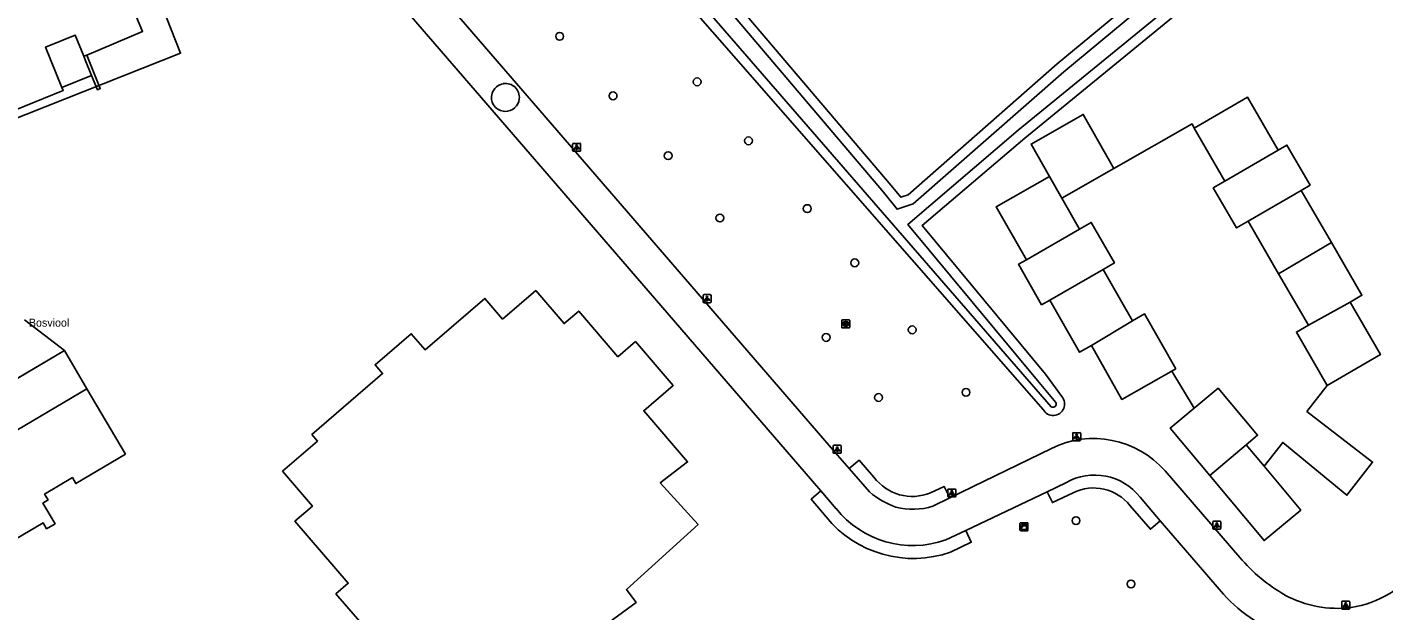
# Model space of a CAD drawing. Extents: x 156664 to 157568, y 383571 to 384421.
# Drawn here: x 156803.6 to 156973.2, y 383759.7 to 383832.6 of the extents above; entities that cross this region are included whole.
import ezdxf

# ---------------------------------------------------------------- set-up
doc = ezdxf.new("R2010")
doc.units = 0
for name, color, linetype in [('IMGEO_Berm_open', 7, 'Continuous'), ('IMGEO_Boom', 7, 'Continuous'), ('IMGEO_Groenvoorziening', 7, 'Continuous'), ('IMGEO_Kast', 7, 'Continuous'), ('IMGEO_Lichtpunt', 7, 'Continuous'), ('IMGEO_Muur', 7, 'Continuous'), ('IMGEO_Openbare_ruimte_label', 7, 'Continuous'), ('IMGEO_Pand', 7, 'Continuous'), ('IMGEO_Pand_overbouw', 7, 'Continuous'), ('IMGEO_Pand_vergunning_verleend', 7, 'Continuous'), ('IMGEO_Rijbaan_lokaal_gesloten', 7, 'Continuous'), ('IMGEO_Rijbaan_lokaal_open', 7, 'Continuous'), ('IMGEO_Rioolput', 7, 'Continuous'), ('IMGEO_Voetpad_op_trap', 7, 'Continuous'), ('IMGEO_Waterloop', 7, 'Continuous')]:
    doc.layers.add(name, color=color, linetype=linetype)

msp = doc.modelspace()

# ---------------------------------------------------------------- linework, layer by layer
at = {"layer": 'IMGEO_Berm_open'}
for points in [[(156906.37, 383777.46), (156907.59, 383778.51), (156909.46, 383776.35)], [(156903.48, 383771.4), (156901.63, 383773.6), (156902.83, 383774.64)], [(156916.53, 383774.41), (156918.22, 383775.22), (156918.95, 383773.77)], [(156934.36, 383774.42), (156931.77, 383773.19), (156931.1, 383774.53)], [(156945.24, 383770.91), (156944.02, 383769.87), (156941.49, 383772.79)], [(156920.96, 383769.71), (156921.62, 383768.24), (156919.03, 383767.01)]]:
    msp.add_lwpolyline(points, dxfattribs=at)
for centre, radius, start, end in [((156914.26, 383779.97), 6.01, 217.0535, 292.2663), ((156936.92, 383769.23), 5.79, 38.0194, 116.3179), ((156914.36, 383780.2), 13.99, 218.969, 289.5075)]:
    msp.add_arc(centre, radius, start, end, dxfattribs=at)
at = {"layer": 'IMGEO_Boom'}
for centre in [(156870.17, 383831.43), (156887.36, 383825.74), (156876.85, 383823.99), (156893.78, 383818.38), (156883.74, 383816.52), (156901.12, 383809.91), (156890.2, 383808.74), (156907.06, 383803.13), (156903.48, 383793.82), (156914.24, 383794.77), (156920.97, 383786.96), (156910.03, 383786.31), (156934.71, 383770.94), (156941.59, 383763.03)]:
    msp.add_circle(centre, 0.489, dxfattribs=at)
at = {"layer": 'IMGEO_Groenvoorziening'}
for points in [[(156851.52, 383893.46), (156854.87, 383880.1), (156855.95, 383876.48), (156875.13, 383855.23), (156891.46, 383836.51), (156911.62, 383812.79), (156912.8, 383811.32), (156913.72, 383811.62), (156932.37, 383827.97), (156950.38, 383842.94), (156962.3, 383852.37), (156962.64, 383852.87), (156967.11, 383858.58), (156983.42, 383879.38)], [(156930.61, 383784.8), (156881.09, 383841.39), (156853.84, 383872.65), (156852.3, 383874.71), (156848.11, 383890.33), (156847.87, 383891.87)], [(156968.21, 383852.09), (156968.15, 383852.02), (156968.1, 383851.94), (156968.04, 383851.87), (156967.54, 383851.36), (156947.1, 383834.06), (156928.3, 383818.71), (156915.48, 383807.78), (156930.92, 383789.21), (156932.93, 383786.44)]]:
    msp.add_lwpolyline(points, dxfattribs=at)
msp.add_arc((156931.86, 383785.5), 1.43, 208.972, 41.1243, dxfattribs=at)
at = {"layer": 'IMGEO_Kast'}
for p, q in [((156927.71, 383769.76), (156927.71, 383770.6)), ((156927.71, 383770.6), (156927.71, 383769.76)), ((156927.79, 383770.68), (156928.63, 383770.68)), ((156928.63, 383770.68), (156927.79, 383770.68)), ((156928.71, 383770.61), (156928.71, 383769.77)), ((156928.71, 383769.77), (156928.71, 383770.61)), ((156928.64, 383769.68), (156927.8, 383769.68)), ((156927.8, 383769.68), (156928.64, 383769.68))]:
    msp.add_line(p, q, dxfattribs=at)
for points in [[(156927.91, 383770.47), (156928.51, 383770.47), (156928.51, 383770.39), (156927.91, 383770.39), (156927.91, 383770.47)], [(156927.91, 383770.3), (156928.51, 383770.3), (156928.51, 383769.81), (156927.91, 383769.81), (156927.91, 383770.3)]]:
    msp.add_lwpolyline(points, dxfattribs=at)
msp.add_circle((156927.99, 383770.15), 0.0377, dxfattribs=at)
for centre, start, end in [((156927.79, 383770.6), 92.4484, 184.2845), ((156927.79, 383770.6), 92.4484, 184.2845), ((156928.63, 383770.6), 2.4484, 94.2845), ((156928.63, 383770.6), 2.4484, 94.2845), ((156927.79, 383769.76), 182.4484, 274.2845), ((156927.79, 383769.76), 182.4484, 274.2845), ((156928.63, 383769.76), 272.4484, 4.2845), ((156928.63, 383769.76), 272.4484, 4.2845)]:
    msp.add_arc(centre, 0.0779, start, end, dxfattribs=at)
at = {"layer": 'IMGEO_Lichtpunt'}
for p, q in [((156871.8, 383817.97), (156871.8, 383817.16)), ((156871.8, 383817.97), (156871.8, 383817.16)), ((156872.7, 383818.06), (156871.9, 383818.06)), ((156872.7, 383818.06), (156871.9, 383818.06)), ((156872.8, 383817.16), (156872.8, 383817.97)), ((156872.8, 383817.16), (156872.8, 383817.97)), ((156871.9, 383817.07), (156872.7, 383817.07)), ((156871.9, 383817.07), (156872.7, 383817.07)), ((156888.1, 383799.06), (156888.1, 383798.26)), ((156888.1, 383799.06), (156888.1, 383798.26)), ((156889, 383799.16), (156888.2, 383799.16)), ((156889, 383799.16), (156888.2, 383799.16)), ((156888.2, 383798.16), (156889, 383798.16)), ((156888.2, 383798.16), (156889, 383798.16)), ((156889.1, 383798.26), (156889.1, 383799.06)), ((156889.1, 383798.26), (156889.1, 383799.06)), ((156934.3, 383781.83), (156934.3, 383781.02)), ((156934.3, 383781.83), (156934.3, 383781.02)), ((156935.2, 383781.92), (156934.39, 383781.92)), ((156935.2, 383781.92), (156934.39, 383781.92)), ((156934.39, 383780.92), (156935.2, 383780.92)), ((156934.39, 383780.92), (156935.2, 383780.92)), ((156935.3, 383781.02), (156935.3, 383781.83)), ((156935.3, 383781.02), (156935.3, 383781.83)), ((156904.37, 383780.26), (156904.37, 383779.45)), ((156904.37, 383780.26), (156904.37, 383779.45)), ((156905.27, 383780.35), (156904.46, 383780.35)), ((156905.27, 383780.35), (156904.46, 383780.35)), ((156904.46, 383779.36), (156905.27, 383779.36)), ((156904.46, 383779.36), (156905.27, 383779.36)), ((156905.36, 383779.45), (156905.36, 383780.26)), ((156905.36, 383779.45), (156905.36, 383780.26)), ((156918.69, 383774.79), (156918.69, 383773.98)), ((156918.69, 383774.79), (156918.69, 383773.98)), ((156919.59, 383774.88), (156918.79, 383774.88)), ((156919.59, 383774.88), (156918.79, 383774.88)), ((156918.79, 383773.89), (156919.59, 383773.89)), ((156918.79, 383773.89), (156919.59, 383773.89)), ((156919.69, 383773.98), (156919.69, 383774.79)), ((156919.69, 383773.98), (156919.69, 383774.79)), ((156951.82, 383770.77), (156951.82, 383769.96)), ((156951.82, 383770.77), (156951.82, 383769.96)), ((156952.72, 383770.87), (156951.92, 383770.87)), ((156952.72, 383770.87), (156951.92, 383770.87)), ((156952.82, 383769.96), (156952.82, 383770.77)), ((156952.82, 383769.96), (156952.82, 383770.77)), ((156951.92, 383769.87), (156952.72, 383769.87)), ((156951.92, 383769.87), (156952.72, 383769.87)), ((156967.93, 383760.79), (156967.93, 383759.98)), ((156967.93, 383760.79), (156967.93, 383759.98)), ((156968.83, 383760.88), (156968.02, 383760.88)), ((156968.83, 383760.88), (156968.02, 383760.88)), ((156968.92, 383759.98), (156968.92, 383760.79)), ((156968.92, 383759.98), (156968.92, 383760.79)), ((156968.02, 383759.89), (156968.83, 383759.89)), ((156968.02, 383759.89), (156968.83, 383759.89))]:
    msp.add_line(p, q, dxfattribs=at)
for points in [[(156872.18, 383817.63), (156872.21, 383817.61), (156872.03, 383817.34), (156871.99, 383817.37), (156872.18, 383817.63)], [(156872.28, 383817.59), (156872.33, 383817.59), (156872.33, 383817.26), (156872.28, 383817.26), (156872.28, 383817.59)], [(156872.39, 383817.61), (156872.43, 383817.63), (156872.61, 383817.37), (156872.57, 383817.34), (156872.39, 383817.61)], [(156888.48, 383798.73), (156888.51, 383798.7), (156888.33, 383798.44), (156888.29, 383798.46), (156888.48, 383798.73)], [(156888.58, 383798.68), (156888.62, 383798.68), (156888.62, 383798.36), (156888.58, 383798.36), (156888.58, 383798.68)], [(156888.69, 383798.7), (156888.73, 383798.73), (156888.91, 383798.46), (156888.87, 383798.44), (156888.69, 383798.7)], [(156934.67, 383781.49), (156934.71, 383781.46), (156934.52, 383781.2), (156934.49, 383781.23), (156934.67, 383781.49)], [(156934.77, 383781.44), (156934.82, 383781.44), (156934.82, 383781.12), (156934.77, 383781.12), (156934.77, 383781.44)], [(156934.88, 383781.46), (156934.92, 383781.49), (156935.11, 383781.23), (156935.07, 383781.2), (156934.88, 383781.46)], [(156904.74, 383779.92), (156904.78, 383779.89), (156904.59, 383779.63), (156904.55, 383779.66), (156904.74, 383779.92)], [(156904.84, 383779.87), (156904.89, 383779.87), (156904.89, 383779.55), (156904.84, 383779.55), (156904.84, 383779.87)], [(156904.95, 383779.89), (156904.99, 383779.92), (156905.18, 383779.66), (156905.14, 383779.63), (156904.95, 383779.89)], [(156919.07, 383774.45), (156919.1, 383774.42), (156918.92, 383774.16), (156918.88, 383774.19), (156919.07, 383774.45)], [(156919.17, 383774.4), (156919.22, 383774.4), (156919.22, 383774.08), (156919.17, 383774.08), (156919.17, 383774.4)], [(156919.28, 383774.42), (156919.32, 383774.45), (156919.5, 383774.19), (156919.46, 383774.16), (156919.28, 383774.42)], [(156952.2, 383770.43), (156952.24, 383770.41), (156952.05, 383770.14), (156952.01, 383770.17), (156952.2, 383770.43)], [(156952.41, 383770.41), (156952.45, 383770.43), (156952.63, 383770.17), (156952.6, 383770.14), (156952.41, 383770.41)], [(156952.3, 383770.39), (156952.35, 383770.39), (156952.35, 383770.06), (156952.3, 383770.06), (156952.3, 383770.39)], [(156968.3, 383760.45), (156968.34, 383760.42), (156968.15, 383760.16), (156968.11, 383760.19), (156968.3, 383760.45)], [(156968.4, 383760.4), (156968.45, 383760.4), (156968.45, 383760.08), (156968.4, 383760.08), (156968.4, 383760.4)], [(156968.51, 383760.42), (156968.55, 383760.45), (156968.74, 383760.19), (156968.7, 383760.16), (156968.51, 383760.42)]]:
    msp.add_lwpolyline(points, dxfattribs=at)
for centre in [(156872.3, 383817.77), (156888.6, 383798.86), (156934.8, 383781.62), (156904.87, 383780.06), (156919.19, 383774.59), (156952.32, 383770.57), (156968.43, 383760.59)]:
    msp.add_circle(centre, 0.0994, dxfattribs=at)
for centre, start, end in [((156871.9, 383817.97), 90, 180), ((156871.9, 383817.97), 90, 180), ((156872.7, 383817.97), 0, 90), ((156872.7, 383817.97), 0, 90), ((156871.9, 383817.16), 180, 270), ((156871.9, 383817.16), 180, 270), ((156872.7, 383817.16), 270, 0), ((156872.7, 383817.16), 270, 360), ((156888.2, 383799.06), 90, 180), ((156888.2, 383799.06), 90, 180), ((156888.2, 383798.26), 180, 270), ((156888.2, 383798.26), 180, 270), ((156889, 383799.06), 0, 90), ((156889, 383799.06), 0, 90), ((156889, 383798.26), 270, 0), ((156889, 383798.26), 270, 360), ((156934.39, 383781.83), 90, 180), ((156934.39, 383781.83), 90, 180), ((156934.39, 383781.02), 180, 270), ((156934.39, 383781.02), 180, 270), ((156935.2, 383781.83), 0, 90), ((156935.2, 383781.83), 0, 90), ((156935.2, 383781.02), 270, 0), ((156935.2, 383781.02), 270, 360), ((156904.46, 383780.26), 90, 180), ((156904.46, 383780.26), 90, 180), ((156904.46, 383779.45), 180, 270), ((156904.46, 383779.45), 180, 270), ((156905.27, 383780.26), 0, 90), ((156905.27, 383780.26), 0, 90), ((156905.27, 383779.45), 270, 0), ((156905.27, 383779.45), 270, 360), ((156918.79, 383774.79), 90, 180), ((156918.79, 383774.79), 90, 180), ((156918.79, 383773.98), 180, 270), ((156918.79, 383773.98), 180, 270), ((156919.59, 383774.79), 0, 90), ((156919.59, 383774.79), 0, 90), ((156919.59, 383773.98), 270, 0), ((156919.59, 383773.98), 270, 360), ((156951.92, 383770.77), 90, 180), ((156951.92, 383770.77), 90, 180), ((156952.72, 383770.77), 0, 90), ((156952.72, 383770.77), 0, 90), ((156951.92, 383769.96), 180, 270), ((156951.92, 383769.96), 180, 270), ((156952.72, 383769.96), 270, 0), ((156952.72, 383769.96), 270, 360), ((156968.02, 383760.79), 90, 180), ((156968.02, 383760.79), 90, 180), ((156968.83, 383760.79), 0, 90), ((156968.83, 383760.79), 0, 90), ((156968.02, 383759.98), 180, 270), ((156968.02, 383759.98), 180, 270), ((156968.83, 383759.98), 270, 0), ((156968.83, 383759.98), 270, 360)]:
    msp.add_arc(centre, 0.0946, start, end, dxfattribs=at)
at = {"layer": 'IMGEO_Muur'}
for points in [[(156810.69, 383828.93), (156810.88, 383828.48), (156811.66, 383826.54)], [(156811.66, 383826.54), (156812.39, 383824.75), (156812.75, 383824.9), (156811.06, 383829.07)]]:
    msp.add_lwpolyline(points, dxfattribs=at)
at = {"layer": 'IMGEO_Pand'}
for points in [[(156807.97, 383825.04), (156808.12, 383824.67), (156800.74, 383821.68), (156799.6, 383824.5), (156795.42, 383822.79), (156793.14, 383828.33), (156790.36, 383827.19), (156787.63, 383833.86), (156788.46, 383834.21), (156786.93, 383837.92), (156786.1, 383837.58), (156783.38, 383844.24), (156784.76, 383844.81), (156780.2, 383855.94), (156794.06, 383861.61), (156795.92, 383862.38), (156798.21, 383863.31), (156804.04, 383865.7)], [(156810.75, 383865.21), (156812.32, 383865.86), (156814.59, 383860.3), (156817.38, 383861.45), (156822.06, 383849.94), (156821.46, 383849.69), (156823.74, 383844.14), (156820.2, 383842.68), (156822.5, 383837.14), (156816.87, 383834.83), (156818.05, 383832.04), (156811.06, 383829.07)], [(156810.69, 383828.93), (156809.62, 383831.57), (156805.93, 383830.08), (156807.97, 383825.04)], [(156811.06, 383829.07), (156810.69, 383828.93)], [(156800.36, 383781.07), (156811.07, 383787.41), (156815.9, 383779.24)], [(156815.9, 383779.24), (156809.71, 383775.57), (156809.27, 383776.31), (156805.8, 383774.26), (156806.24, 383773.52), (156805.58, 383773.12), (156807.1, 383770.55), (156806.05, 383769.93), (156805.61, 383770.67), (156802.14, 383768.64)]]:
    msp.add_lwpolyline(points, dxfattribs=at)
at = {"layer": 'IMGEO_Pand_overbouw'}
msp.add_lwpolyline([(156808.27, 383792.17), (156797.55, 383785.84), (156799.07, 383783.25), (156783.98, 383774.32), (156782.46, 383776.91), (156766.58, 383767.51), (156769.38, 383762.77), (156785.21, 383772.14), (156786.73, 383769.55), (156801.89, 383778.49), (156800.36, 383781.07), (156811.07, 383787.41)], close=True, dxfattribs=at)
at = {"layer": 'IMGEO_Pand_vergunning_verleend'}
for points in [[(156780.47, 383854.21), (156810.42, 383866.07), (156813.71, 383857.94), (156816.75, 383859.15), (156823.56, 383841.94), (156820.43, 383840.7), (156822.3, 383835.97), (156820.45, 383835.23), (156822.8, 383829.31), (156801.04, 383820.7), (156799.83, 383823.75), (156795.74, 383822.13), (156793.48, 383827.86), (156790.01, 383826.48), (156783.66, 383842.52), (156784.9, 383843.01), (156780.47, 383854.21)], [(156949.49, 383819.94), (156956.15, 383823.81), (156959.98, 383817.2)], [(156931.39, 383813.92), (156929.09, 383817.97), (156935.61, 383821.68), (156939.45, 383814.93)], [(156939.45, 383814.93), (156949.22, 383820.49), (156949.49, 383819.94)], [(156949.49, 383819.94), (156953.32, 383813.34)], [(156953.32, 383813.34), (156959.98, 383817.2)], [(156959.98, 383817.2), (156961.07, 383817.84), (156963.97, 383812.84), (156962.85, 383812.19)], [(156932.94, 383811.23), (156939.45, 383814.93)], [(156939.45, 383814.93), (156939.45, 383814.93), (156932.94, 383811.23)], [(156928.52, 383803.51), (156924.75, 383810.15), (156931.39, 383813.92)], [(156932.94, 383811.23), (156931.39, 383813.92)], [(156953.32, 383813.34), (156951.87, 383812.5), (156954.78, 383807.49), (156956.23, 383808.33)], [(156935.14, 383807.36), (156932.94, 383811.23)], [(156956.23, 383808.33), (156962.85, 383812.19)], [(156962.85, 383812.19), (156966.64, 383805.66)], [(156938.11, 383802.32), (156939.51, 383803.12), (156936.62, 383808.19), (156935.14, 383807.36)], [(156956.23, 383808.33), (156960.03, 383801.78)], [(156935.14, 383807.36), (156928.52, 383803.51)], [(156960.03, 383801.78), (156966.64, 383805.66)], [(156966.64, 383805.66), (156970.45, 383799.09), (156968.97, 383798.23)], [(156931.45, 383798.49), (156930.41, 383797.89), (156927.54, 383802.95), (156928.52, 383803.51)], [(156938.11, 383802.32), (156931.45, 383798.49)], [(156941.77, 383795.9), (156938.11, 383802.32)], [(156960.03, 383801.78), (156963.76, 383795.35)], [(156835.53, 383777.13), (156839.89, 383780.88), (156839.2, 383781.69), (156848.05, 383789.31), (156847.11, 383790.4), (156851.63, 383794.28), (156853.36, 383792.27), (156860.83, 383798.69), (156863.05, 383796.11), (156867.18, 383799.67), (156870.73, 383795.54), (156872.56, 383797.11), (156877.46, 383791.41), (156879.64, 383793.29), (156884.35, 383787.8), (156880.69, 383784.66), (156886.17, 383778.28), (156882.75, 383775.65), (156887.48, 383770.46), (156878.55, 383762.33), (156879.73, 383760.73), (156871.37, 383754.59)], [(156936.63, 383792.81), (156935.16, 383791.97), (156931.45, 383798.49)], [(156963.76, 383795.35), (156968.97, 383798.23)], [(156968.97, 383798.23), (156972.77, 383791.68), (156966.12, 383787.83)], [(156941.77, 383795.9), (156936.63, 383792.81)], [(156947.18, 383789.89), (156943.28, 383796.76), (156941.77, 383795.9)], [(156963.76, 383795.35), (156962.26, 383794.48), (156966.12, 383787.83)], [(156947.18, 383789.89), (156940.46, 383786.07), (156936.63, 383792.81)], [(156949.49, 383785), (156946.71, 383789.62), (156947.18, 383789.89)], [(156955.98, 383780.41), (156957.41, 383781.6), (156952.48, 383787.5), (156949.49, 383785)], [(156966.12, 383787.83), (156963.58, 383784.58), (156971.78, 383778.26), (156968.58, 383774.11), (156960.55, 383780.7), (156958.23, 383777.73)], [(156951.44, 383776.57), (156946.49, 383782.49), (156949.49, 383785)], [(156955.98, 383780.41), (156951.44, 383776.57)], [(156958.23, 383777.73), (156958.22, 383777.72), (156955.98, 383780.41)], [(156955.98, 383780.41), (156958.23, 383777.73)], [(156958.23, 383777.73), (156962.8, 383772.25), (156958.23, 383768.44), (156951.44, 383776.57)], [(156846.52, 383756.78), (156842.21, 383761.79), (156843.75, 383763.11), (156837.08, 383770.87), (156839.28, 383772.76), (156835.53, 383777.13)]]:
    msp.add_lwpolyline(points, dxfattribs=at)
at = {"layer": 'IMGEO_Rijbaan_lokaal_gesloten'}
for centre, radius, start, end in [((156863.39, 383823.78), 1.74, 130.0856, 169.5908), ((156863.4, 383823.8), 1.73, 98.7141, 130.6426), ((156863.4, 383823.8), 1.74, 353.8037, 98.8143), ((156863.39, 383823.79), 1.74, 169.6525, 268.2313), ((156863.39, 383823.8), 1.75, 311.4273, 353.6497), ((156863.39, 383823.79), 1.74, 268.2893, 311.8666)]:
    msp.add_arc(centre, radius, start, end, dxfattribs=at)
at = {"layer": 'IMGEO_Rijbaan_lokaal_open'}
for points in [[(156820.25, 383877.09), (156862.92, 383827.69), (156866.64, 383823.38), (156904.91, 383779.13), (156906.37, 383777.46)], [(156822.23, 383867.92), (156859.63, 383824.66), (156863.33, 383820.38), (156901.78, 383775.88), (156902.83, 383774.64)], [(156803.29, 383796.01), (156808.28, 383792.18), (156766.72, 383767.6)], [(156918.95, 383773.77), (156931.63, 383779.95)], [(156908.89, 383774.52), (156906.37, 383777.46)], [(156931.1, 383774.53), (156933.46, 383775.67)], [(156945.85, 383777.14), (156955.18, 383766.34)], [(156902.83, 383774.64), (156904.73, 383772.43)], [(156920.96, 383769.71), (156931.1, 383774.53)], [(156942.73, 383773.87), (156945.24, 383770.91)], [(156918.95, 383773.77), (156916.83, 383772.74)], [(156945.24, 383770.91), (156953.13, 383761.76)], [(156918.43, 383768.53), (156920.96, 383769.71)]]:
    msp.add_lwpolyline(points, dxfattribs=at)
for centre, radius, start, end in [((156936.92, 383769.3), 11.89, 41.2931, 116.3849), ((156937.05, 383769.42), 7.21, 38.1257, 119.8685), ((156916.12, 383783.25), 11.33, 230.4057, 249.8257), ((156914.32, 383780.11), 12.29, 218.648, 289.5186), ((156914.29, 383781.08), 8.72, 256.156, 286.9403), ((156971.37, 383780.07), 21.22, 220.3019, 240.2427), ((156966.98, 383773.49), 13.57, 279.0659, 321.884), ((156967.28, 383774.49), 19.03, 221.9777, 237.3164), ((156967.43, 383773.9), 13.92, 241.6944, 276.9468)]:
    msp.add_arc(centre, radius, start, end, dxfattribs=at)
at = {"layer": 'IMGEO_Rioolput'}
for p, q in [((156905.43, 383795.08), (156905.43, 383795.93)), ((156905.51, 383796.01), (156906.36, 383796.01)), ((156906.44, 383795.93), (156906.44, 383795.08)), ((156906.36, 383795.01), (156905.51, 383795.01)), ((156905.92, 383795.79), (156905.95, 383795.79)), ((156905.94, 383795.23), (156905.92, 383795.23))]:
    msp.add_line(p, q, dxfattribs=at)
for points in [[(156905.43, 383795.08), (156905.43, 383795.93)], [(156905.51, 383796.01), (156906.36, 383796.01)], [(156906.44, 383795.93), (156906.44, 383795.08)], [(156906.36, 383795.01), (156905.51, 383795.01)], [(156906.02, 383795.71), (156905.77, 383795.71), (156905.77, 383795.31)], [(156905.77, 383795.31), (156905.9, 383795.31), (156905.9, 383795.47), (156905.91, 383795.47)], [(156905.95, 383795.63), (156905.9, 383795.63), (156905.9, 383795.55)], [(156905.9, 383795.55), (156905.95, 383795.55)], [(156905.95, 383795.44), (156906.02, 383795.31), (156906.16, 383795.31), (156906.1, 383795.43)]]:
    msp.add_lwpolyline(points, dxfattribs=at)
for centre, radius, start, end in [((156905.51, 383795.93), 0.0765, 91.552, 178.448), ((156905.51, 383795.93), 0.0765, 91.552, 178.448), ((156906.36, 383795.93), 0.0765, 1.552, 88.448), ((156906.36, 383795.93), 0.0765, 1.552, 88.448), ((156905.51, 383795.08), 0.0765, 181.552, 268.448), ((156905.51, 383795.08), 0.0765, 181.552, 268.448), ((156905.9, 383795.42), 0.0533, 26.0293, 88.6989), ((156905.95, 383795.53), 0.0964, 77.0061, 93.1865), ((156905.93, 383795.74), 0.19, 274.7715, 282.9687), ((156905.97, 383795.59), 0.0378, 276.6634, 79.6772), ((156906.02, 383795.6), 0.109, 350.3612, 89.416), ((156906.02, 383795.6), 0.112, 277.5842, 350.9817), ((156906, 383795.38), 0.108, 29.5134, 73.7905), ((156906.36, 383795.08), 0.0765, 271.552, 358.448), ((156906.36, 383795.08), 0.0765, 271.552, 358.448)]:
    msp.add_arc(centre, radius, start, end, dxfattribs=at)
for centre, major_axis, ratio, start_param, end_param in [((156905.92, 383795.51), (-0.387, 0.002), 0.722429, 4.712389, 7.853982), ((156905.95, 383795.51), (-0.39, 0.002), 0.717154, 1.570796, 4.712389)]:
    msp.add_ellipse(centre, major_axis=major_axis, ratio=ratio, start_param=start_param, end_param=end_param, dxfattribs=at)
at = {"layer": 'IMGEO_Voetpad_op_trap'}
msp.add_lwpolyline([(156807.97, 383825.04), (156811.66, 383826.54)], dxfattribs=at)
at = {"layer": 'IMGEO_Waterloop'}
for points in [[(156931.62, 383785.15), (156882.05, 383842.23), (156854.83, 383873.45), (156853.47, 383875.28), (156849.46, 383890.63), (156849.07, 383892.88)], [(156850.28, 383893.2), (156853.64, 383879.76), (156854.82, 383875.84), (156874.18, 383854.39), (156890.49, 383835.68), (156910.64, 383811.98), (156912.36, 383809.83), (156914.36, 383810.5), (156933.19, 383827), (156951.18, 383841.95), (156963.24, 383851.49), (156963.69, 383852.15)], [(156986.12, 383878.75), (156986.22, 383878.47), (156986.2, 383878.22), (156986.14, 383877.96), (156986.06, 383877.69), (156968.38, 383854.42), (156967.1, 383852.73), (156966.67, 383852.3), (156946.29, 383835.04), (156927.48, 383819.69), (156913.7, 383807.94), (156929.91, 383788.43), (156932.19, 383785.7)]]:
    msp.add_lwpolyline(points, dxfattribs=at)
msp.add_arc((156931.84, 383785.5), 0.406, 238.47, 30.3975, dxfattribs=at)

# ---------------------------------------------------------------- texts
at = {"layer": 'IMGEO_Openbare_ruimte_label'}
msp.add_text('Bosviool', height=1, dxfattribs=at).set_placement((156803.83, 383795.16))

doc.saveas('drawing.dxf')
